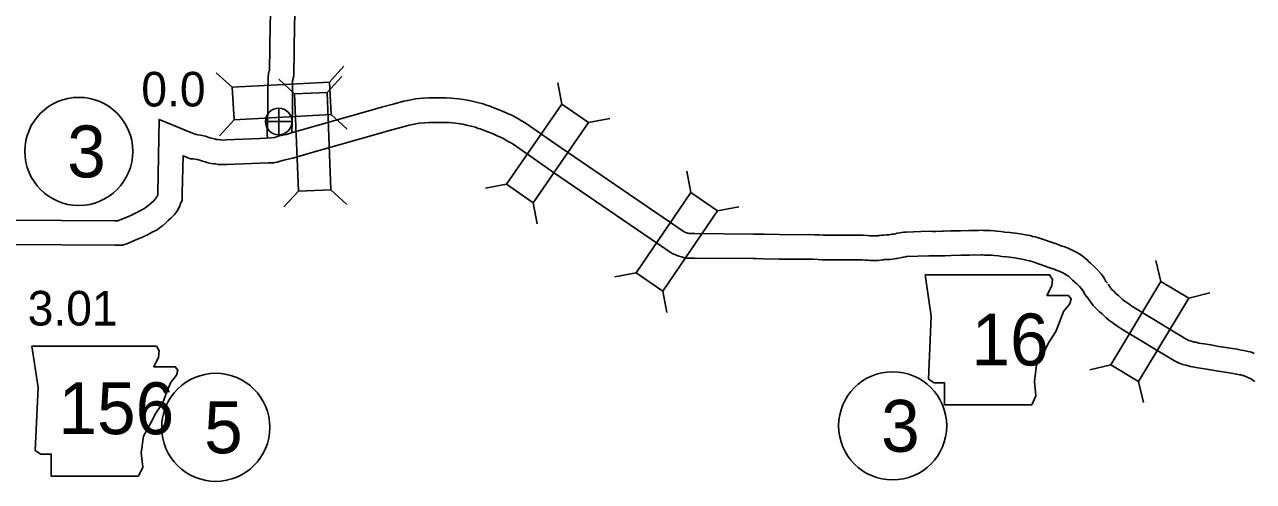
# Model space of a CAD drawing. Extents: x -939622 to -934245, y 1383184 to 1385301.
# Drawn here: x -936322.89 to -936277.86, y 1384937.85 to 1384954.58 of the extents above; entities that cross this region are included whole.
import ezdxf

# ---------------------------------------------------------------- set-up
doc = ezdxf.new("R2010")
doc.units = 0
for name, color, linetype in [('10', 7, 'Continuous'), ('20', 7, 'Continuous'), ('21', 7, 'Continuous'), ('25', 7, 'Continuous'), ('26', 7, 'Continuous'), ('27', 7, 'Continuous')]:
    doc.layers.add(name, color=color, linetype=linetype)

msp = doc.modelspace()

# ---------------------------------------------------------------- linework, layer by layer
at = {"layer": '10'}
for points in [[(-936313.995, 1384950.422), (-936314.003, 1384950.578), (-936313.981, 1384951.478), (-936313.981, 1384952.212), (-936313.969, 1384952.568), (-936313.97, 1384952.68), (-936313.939, 1384952.86), (-936313.918, 1384952.887), (-936313.897, 1384954.61), (-936313.798, 1384957.069), (-936313.777, 1384957.809), (-936313.741, 1384958.87), (-936313.708, 1384959.624), (-936313.699, 1384959.744), (-936313.68, 1384959.94), (-936313.638, 1384960.151), (-936313.579, 1384960.357), (-936313.523, 1384960.536), (-936313.43, 1384960.751), (-936313.332, 1384960.934), (-936313.274, 1384961.026)], [(-936313.102, 1384950.609), (-936313.081, 1384951.467), (-936313.081, 1384952.197), (-936313.07, 1384952.523), (-936313.021, 1384952.708), (-936312.997, 1384954.586), (-936312.898, 1384957.039), (-936312.878, 1384957.782), (-936312.842, 1384958.835), (-936312.81, 1384959.571), (-936312.803, 1384959.667), (-936312.789, 1384959.807), (-936312.762, 1384959.939), (-936312.716, 1384960.1), (-936312.679, 1384960.222), (-936312.62, 1384960.357), (-936312.553, 1384960.482), (-936312.426, 1384960.684)], [(-936312.901, 1384950.676), (-936310.145, 1384951.458), (-936309.817, 1384951.553), (-936309.39, 1384951.671), (-936309.001, 1384951.775), (-936308.782, 1384951.816), (-936308.567, 1384951.857), (-936308.297, 1384951.883), (-936308.08, 1384951.895), (-936307.851, 1384951.893), (-936307.677, 1384951.897), (-936307.461, 1384951.893), (-936307.275, 1384951.887), (-936306.991, 1384951.861), (-936306.807, 1384951.839), (-936306.672, 1384951.817), (-936306.492, 1384951.778), (-936306.299, 1384951.731), (-936306.093, 1384951.674), (-936305.965, 1384951.627), (-936305.919, 1384951.611), (-936305.84, 1384951.587), (-936305.702, 1384951.535), (-936305.6, 1384951.497), (-936305.438, 1384951.433), (-936305.337, 1384951.39), (-936305.241, 1384951.348), (-936305.146, 1384951.301), (-936305.103, 1384951.282), (-936304.994, 1384951.238), (-936304.891, 1384951.177), (-936304.788, 1384951.122), (-936304.703, 1384951.071), (-936304.632, 1384951.031), (-936304.508, 1384950.958), (-936303.502, 1384950.251), (-936303.002, 1384949.907)], [(-936323.472, 1384947.423), (-936319.581, 1384947.398), (-936319.473, 1384947.398), (-936319.464, 1384947.398), (-936319.449, 1384947.403), (-936319.265, 1384947.477), (-936319.104, 1384947.544), (-936318.95, 1384947.613), (-936318.822, 1384947.674), (-936318.621, 1384947.785), (-936318.519, 1384947.831), (-936318.473, 1384947.87), (-936318.39, 1384947.931), (-936318.303, 1384947.999), (-936318.234, 1384948.064), (-936318.161, 1384948.13), (-936318.119, 1384948.175), (-936318.095, 1384948.201), (-936318.069, 1384948.236), (-936318.043, 1384948.28), (-936318.037, 1384948.292), (-936318.027, 1384948.321), (-936318.015, 1384948.346), (-936318.014, 1384948.423), (-936317.961, 1384951.107), (-936316.74, 1384950.607), (-936316.605, 1384950.553), (-936316.527, 1384950.541), (-936316.429, 1384950.528), (-936316.342, 1384950.51), (-936316.267, 1384950.489), (-936316.196, 1384950.467), (-936316.139, 1384950.448), (-936316.105, 1384950.437), (-936316.051, 1384950.426), (-936315.938, 1384950.393), (-936315.866, 1384950.376), (-936315.86, 1384950.375), (-936315.82, 1384950.375), (-936315.707, 1384950.356), (-936315.586, 1384950.352), (-936315.502, 1384950.353), (-936314.269, 1384950.408), (-936313.858, 1384950.428), (-936313.729, 1384950.45), (-936313.651, 1384950.474), (-936313.559, 1384950.5), (-936313.294, 1384950.557), (-936313.11, 1384950.614), (-936312.906, 1384950.674)], [(-936312.655, 1384949.81), (-936309.898, 1384950.593), (-936309.572, 1384950.687), (-936309.153, 1384950.803), (-936308.803, 1384950.896), (-936308.616, 1384950.931), (-936308.438, 1384950.965), (-936308.229, 1384950.985), (-936308.058, 1384950.994), (-936307.843, 1384950.993), (-936307.676, 1384950.997), (-936307.484, 1384950.993), (-936307.329, 1384950.988), (-936307.085, 1384950.966), (-936306.932, 1384950.948), (-936306.839, 1384950.933), (-936306.694, 1384950.901), (-936306.525, 1384950.86), (-936306.369, 1384950.817), (-936306.268, 1384950.779), (-936306.199, 1384950.756), (-936306.133, 1384950.736), (-936306.018, 1384950.692), (-936305.921, 1384950.656), (-936305.78, 1384950.6), (-936305.694, 1384950.564), (-936305.62, 1384950.531), (-936305.527, 1384950.486), (-936305.455, 1384950.454), (-936305.396, 1384950.43), (-936305.334, 1384950.393), (-936305.231, 1384950.338), (-936305.153, 1384950.291), (-936305.078, 1384950.25), (-936304.995, 1384950.201), (-936304.017, 1384949.513), (-936303.513, 1384949.165)], [(-936323.483, 1384946.523), (-936319.582, 1384946.498), (-936319.468, 1384946.498), (-936319.419, 1384946.499), (-936319.3, 1384946.506), (-936319.145, 1384946.555), (-936318.923, 1384946.645), (-936318.749, 1384946.718), (-936318.574, 1384946.795), (-936318.41, 1384946.873), (-936318.216, 1384946.98), (-936318.037, 1384947.062), (-936317.917, 1384947.162), (-936317.844, 1384947.216), (-936317.716, 1384947.316), (-936317.625, 1384947.402), (-936317.53, 1384947.487), (-936317.46, 1384947.562), (-936317.4, 1384947.627), (-936317.319, 1384947.737), (-936317.256, 1384947.843), (-936317.209, 1384947.933), (-936317.189, 1384947.989), (-936317.118, 1384948.15), (-936317.115, 1384948.409), (-936317.087, 1384949.776), (-936317.078, 1384949.773), (-936316.938, 1384949.717), (-936316.814, 1384949.665), (-936316.714, 1384949.659), (-936316.655, 1384949.65), (-936316.579, 1384949.64), (-936316.552, 1384949.634), (-936316.519, 1384949.625), (-936316.476, 1384949.612), (-936316.413, 1384949.59), (-936316.328, 1384949.565), (-936316.273, 1384949.553), (-936316.165, 1384949.521), (-936316.057, 1384949.497), (-936315.949, 1384949.475), (-936315.892, 1384949.475), (-936315.796, 1384949.459), (-936315.599, 1384949.452), (-936315.48, 1384949.453), (-936313.968, 1384949.521), (-936313.904, 1384949.521), (-936313.767, 1384949.515), (-936313.711, 1384949.534), (-936313.634, 1384949.538), (-936313.56, 1384949.566), (-936313.522, 1384949.572), (-936313.398, 1384949.61), (-936313.34, 1384949.627), (-936313.067, 1384949.686), (-936312.85, 1384949.752), (-936312.649, 1384949.812)], [(-936303.004, 1384949.908), (-936298.729, 1384946.991), (-936298.677, 1384946.969), (-936298.631, 1384946.952), (-936298.588, 1384946.94), (-936298.54, 1384946.928), (-936298.476, 1384946.927), (-936298.332, 1384946.928), (-936296.188, 1384946.91), (-936296.075, 1384946.909), (-936295.796, 1384946.9), (-936295.23, 1384946.889), (-936294.581, 1384946.886), (-936294.179, 1384946.892), (-936293.959, 1384946.884), (-936293.774, 1384946.876), (-936293.629, 1384946.868), (-936293.54, 1384946.865), (-936293.376, 1384946.868), (-936292.166, 1384946.865), (-936292.004, 1384946.852), (-936291.917, 1384946.844), (-936291.89, 1384946.842), (-936291.837, 1384946.843), (-936291.763, 1384946.841), (-936291.703, 1384946.841), (-936291.679, 1384946.843), (-936291.63, 1384946.846), (-936291.598, 1384946.851), (-936291.537, 1384946.859), (-936291.47, 1384946.868), (-936291.392, 1384946.874), (-936291.313, 1384946.879), (-936291.234, 1384946.881), (-936291.208, 1384946.883), (-936291.167, 1384946.889), (-936291.111, 1384946.9), (-936291.048, 1384946.909), (-936290.989, 1384946.916), (-936290.984, 1384946.917), (-936290.921, 1384946.942), (-936290.809, 1384946.957), (-936290.766, 1384946.962), (-936290.685, 1384946.98), (-936290.583, 1384946.982), (-936289.768, 1384947.01), (-936289.628, 1384947.007), (-936289.506, 1384947.007), (-936289.408, 1384947.009), (-936289.321, 1384947.008), (-936289.27, 1384947.009), (-936289.219, 1384947.013), (-936288.97, 1384947.022), (-936288.601, 1384947.03), (-936288.295, 1384947.04), (-936288.084, 1384947.045), (-936287.936, 1384947.042), (-936287.832, 1384947.048), (-936287.756, 1384947.042), (-936287.682, 1384947.041), (-936287.616, 1384947.037), (-936287.507, 1384947.04), (-936287.366, 1384947.027), (-936287.267, 1384947.015), (-936287.116, 1384947.003), (-936286.969, 1384946.984), (-936286.795, 1384946.964), (-936286.495, 1384946.926), (-936286.336, 1384946.905), (-936286.23, 1384946.883), (-936286.138, 1384946.865), (-936286.04, 1384946.851), (-936285.955, 1384946.825), (-936285.867, 1384946.804), (-936285.778, 1384946.783), (-936285.664, 1384946.744), (-936285.59, 1384946.721), (-936285.202, 1384946.587), (-936285.084, 1384946.548), (-936284.974, 1384946.504), (-936284.877, 1384946.471), (-936284.779, 1384946.437), (-936284.633, 1384946.38), (-936284.431, 1384946.287), (-936284.339, 1384946.231), (-936284.247, 1384946.188), (-936284.151, 1384946.122), (-936284.066, 1384946.055), (-936284.003, 1384946.001), (-936283.936, 1384945.943), (-936283.906, 1384945.904), (-936283.834, 1384945.848), (-936283.721, 1384945.744), (-936283.576, 1384945.605), (-936283.444, 1384945.449), (-936283.375, 1384945.351), (-936283.316, 1384945.269), (-936283.268, 1384945.176), (-936283.216, 1384945.111)], [(-936303.511, 1384949.164), (-936299.159, 1384946.195), (-936299.005, 1384946.131), (-936298.913, 1384946.097), (-936298.823, 1384946.071), (-936298.715, 1384946.044), (-936298.612, 1384946.028), (-936298.479, 1384946.027), (-936298.335, 1384946.028), (-936296.194, 1384946.01), (-936296.092, 1384946.009), (-936295.819, 1384946.001), (-936295.241, 1384945.989), (-936294.577, 1384945.986), (-936294.188, 1384945.992), (-936293.995, 1384945.985), (-936293.82, 1384945.977), (-936293.671, 1384945.969), (-936293.545, 1384945.964), (-936293.367, 1384945.968), (-936292.204, 1384945.965), (-936292.078, 1384945.955), (-936291.997, 1384945.948), (-936291.922, 1384945.941), (-936291.837, 1384945.943), (-936291.779, 1384945.942), (-936291.666, 1384945.94), (-936291.606, 1384945.946), (-936291.529, 1384945.951), (-936291.472, 1384945.96), (-936291.42, 1384945.967), (-936291.379, 1384945.972), (-936291.331, 1384945.976), (-936291.273, 1384945.98), (-936291.19, 1384945.981), (-936291.103, 1384945.988), (-936291.012, 1384946.003), (-936290.961, 1384946.012), (-936290.929, 1384946.017), (-936290.862, 1384946.025), (-936290.742, 1384946.045), (-936290.692, 1384946.064), (-936290.614, 1384946.074), (-936290.575, 1384946.082), (-936290.558, 1384946.083), (-936289.763, 1384946.11), (-936289.638, 1384946.107), (-936289.496, 1384946.107), (-936289.403, 1384946.109), (-936289.316, 1384946.108), (-936289.224, 1384946.11), (-936289.168, 1384946.114), (-936288.944, 1384946.122), (-936288.576, 1384946.13), (-936288.271, 1384946.14), (-936288.081, 1384946.145), (-936287.918, 1384946.142), (-936287.842, 1384946.146), (-936287.798, 1384946.143), (-936287.715, 1384946.142), (-936287.632, 1384946.137), (-936287.537, 1384946.139), (-936287.462, 1384946.132), (-936287.357, 1384946.119), (-936287.208, 1384946.108), (-936287.078, 1384946.091), (-936286.904, 1384946.071), (-936286.609, 1384946.033), (-936286.486, 1384946.017), (-936286.411, 1384946.001), (-936286.287, 1384945.977), (-936286.235, 1384945.97), (-936286.193, 1384945.957), (-936286.076, 1384945.929), (-936286.027, 1384945.917), (-936285.941, 1384945.888), (-936285.87, 1384945.866), (-936285.492, 1384945.735), (-936285.392, 1384945.702), (-936285.285, 1384945.66), (-936285.17, 1384945.62), (-936285.088, 1384945.592), (-936284.986, 1384945.552), (-936284.854, 1384945.491), (-936284.765, 1384945.437), (-936284.698, 1384945.406), (-936284.685, 1384945.396), (-936284.646, 1384945.366), (-936284.498, 1384945.224), (-936284.416, 1384945.161), (-936284.339, 1384945.089), (-936284.233, 1384944.988), (-936284.156, 1384944.896), (-936284.108, 1384944.829), (-936284.086, 1384944.799), (-936284.028, 1384944.684), (-936283.919, 1384944.549)], [(-936283.192, 1384945.078), (-936283.124, 1384944.974), (-936283.088, 1384944.925), (-936283.06, 1384944.892), (-936282.984, 1384944.812), (-936282.897, 1384944.725), (-936282.813, 1384944.654), (-936282.717, 1384944.564), (-936282.664, 1384944.517), (-936282.619, 1384944.479), (-936282.537, 1384944.423), (-936282.436, 1384944.35), (-936282.324, 1384944.273), (-936282.201, 1384944.19), (-936280.326, 1384943.059), (-936280.237, 1384943.017), (-936280.178, 1384942.995), (-936280.093, 1384942.973), (-936280.033, 1384942.955), (-936279.981, 1384942.945), (-936279.864, 1384942.918), (-936279.775, 1384942.907), (-936279.669, 1384942.89), (-936279.428, 1384942.849), (-936279.135, 1384942.796), (-936278.456, 1384942.689), (-936278.314, 1384942.663), (-936278.233, 1384942.646), (-936278.16, 1384942.637), (-936278.053, 1384942.609), (-936277.939, 1384942.582), (-936277.84, 1384942.54)], [(-936283.943, 1384944.581), (-936283.863, 1384944.461), (-936283.8, 1384944.374), (-936283.735, 1384944.295), (-936283.627, 1384944.181), (-936283.506, 1384944.062), (-936283.412, 1384943.982), (-936283.325, 1384943.901), (-936283.256, 1384943.838), (-936283.161, 1384943.759), (-936283.054, 1384943.686), (-936282.954, 1384943.614), (-936282.829, 1384943.528), (-936282.685, 1384943.431), (-936280.752, 1384942.265), (-936280.586, 1384942.186), (-936280.446, 1384942.135), (-936280.338, 1384942.107), (-936280.253, 1384942.081), (-936280.167, 1384942.064), (-936280.019, 1384942.031), (-936279.904, 1384942.016), (-936279.817, 1384942.002), (-936279.583, 1384941.963), (-936279.286, 1384941.909), (-936278.607, 1384941.801), (-936278.484, 1384941.779), (-936278.379, 1384941.758), (-936278.331, 1384941.752), (-936278.27, 1384941.736), (-936278.22, 1384941.724), (-936278.199, 1384941.715), (-936278.092, 1384941.667), (-936278.016, 1384941.636), (-936277.973, 1384941.615), (-936277.918, 1384941.58), (-936277.814, 1384941.506)]]:
    msp.add_lwpolyline(points, dxfattribs=at)
at = {"layer": '20'}
for p, q in [((-936311.722, 1384952.471), (-936311.193, 1384953.06)), ((-936315.281, 1384952.282), (-936315.87, 1384952.811)), ((-936312.997, 1384952.046), (-936313.578, 1384952.584)), ((-936311.81, 1384952.093), (-936311.272, 1384952.674)), ((-936303.209, 1384951.666), (-936303.352, 1384952.445)), ((-936315.218, 1384951.095), (-936315.747, 1384950.506)), ((-936311.659, 1384951.285), (-936311.07, 1384950.755)), ((-936302.23, 1384950.992), (-936301.451, 1384951.136)), ((-936298.479, 1384948.433), (-936298.626, 1384949.211)), ((-936312.858, 1384948.485), (-936313.396, 1384947.903)), ((-936311.671, 1384948.531), (-936311.09, 1384947.993)), ((-936305.231, 1384948.731), (-936306.009, 1384948.588)), ((-936304.252, 1384948.057), (-936304.109, 1384947.279)), ((-936297.498, 1384947.763), (-936296.719, 1384947.91)), ((-936281.253, 1384945.174), (-936281.443, 1384945.943)), ((-936300.488, 1384945.489), (-936301.266, 1384945.342)), ((-936299.506, 1384944.819), (-936299.359, 1384944.041)), ((-936280.236, 1384944.561), (-936279.467, 1384944.751)), ((-936283.094, 1384942.123), (-936283.863, 1384941.932)), ((-936282.077, 1384941.509), (-936281.887, 1384940.74))]:
    msp.add_line(p, q, dxfattribs=at)
for points in [[(-936315.218, 1384951.095), (-936311.659, 1384951.285), (-936311.722, 1384952.471), (-936315.281, 1384952.282)], [(-936312.997, 1384952.046), (-936312.858, 1384948.485), (-936311.671, 1384948.531), (-936311.81, 1384952.093)], [(-936304.252, 1384948.057), (-936302.23, 1384950.992), (-936303.209, 1384951.666), (-936305.231, 1384948.731)], [(-936298.479, 1384948.433), (-936300.488, 1384945.489), (-936299.506, 1384944.819), (-936297.498, 1384947.763)], [(-936282.077, 1384941.509), (-936280.236, 1384944.561), (-936281.253, 1384945.174), (-936283.094, 1384942.123)]]:
    msp.add_lwpolyline(points, close=True, dxfattribs=at)
at = {"layer": '21'}
for points in [[(-936289.896, 1384945.422), (-936289.668, 1384943.899), (-936289.769, 1384941.59), (-936289.566, 1384941.463), (-936289.186, 1384941.463), (-936289.186, 1384940.651), (-936285.988, 1384940.651), (-936285.836, 1384940.981), (-936285.887, 1384941.514), (-936285.81, 1384942.123), (-936285.531, 1384942.605), (-936285.354, 1384942.96), (-936285.1, 1384943.341), (-936284.948, 1384943.747), (-936284.821, 1384944.077), (-936284.592, 1384944.356), (-936284.542, 1384944.534), (-936284.643, 1384944.66), (-936285.43, 1384944.66), (-936285.252, 1384945.016), (-936285.227, 1384945.244), (-936285.332, 1384945.419)], [(-936322.626, 1384942.81), (-936322.397, 1384941.288), (-936322.499, 1384938.978), (-936322.296, 1384938.851), (-936321.915, 1384938.851), (-936321.915, 1384938.039), (-936318.718, 1384938.039), (-936318.565, 1384938.369), (-936318.616, 1384938.902), (-936318.54, 1384939.511), (-936318.261, 1384939.993), (-936318.083, 1384940.349), (-936317.829, 1384940.729), (-936317.677, 1384941.135), (-936317.55, 1384941.465), (-936317.322, 1384941.744), (-936317.271, 1384941.922), (-936317.373, 1384942.049), (-936318.159, 1384942.049), (-936317.982, 1384942.404), (-936317.956, 1384942.633), (-936318.061, 1384942.808)]]:
    msp.add_lwpolyline(points, close=True, dxfattribs=at)
at = {"layer": '26'}
for p, q in [((-936313.58, 1384950.542), (-936313.58, 1384951.517)), ((-936314.067, 1384951.029), (-936313.092, 1384951.029))]:
    msp.add_line(p, q, dxfattribs=at)
msp.add_circle((-936313.58, 1384951.029), 0.487, dxfattribs=at)
at = {"layer": '27'}
for centre in [(-936320.905, 1384949.935), (-936315.887, 1384939.832), (-936291.083, 1384939.887)]:
    msp.add_circle(centre, 1.98, dxfattribs=at)

# ---------------------------------------------------------------- texts
at = {"layer": '21'}
msp.add_text('16', height=1.9008, dxfattribs=at).set_placement((-936288.194, 1384942.098))
msp.add_text('156', height=1.9008, rotation=359.9, dxfattribs=at).set_placement((-936321.652, 1384939.585))
at = {"layer": '25'}
for s, p in [('0.0', (-936318.615, 1384951.581)), ('3.01', (-936322.779, 1384943.56))]:
    msp.add_text(s, height=1.2672, dxfattribs=at).set_placement(p)
at = {"layer": '27'}
for s, p in [('3', (-936321.332, 1384948.986)), ('5', (-936316.314, 1384938.883)), ('3', (-936291.509, 1384938.938))]:
    msp.add_text(s, height=1.901, rotation=359.9, dxfattribs=at).set_placement(p)

doc.saveas('drawing.dxf')
